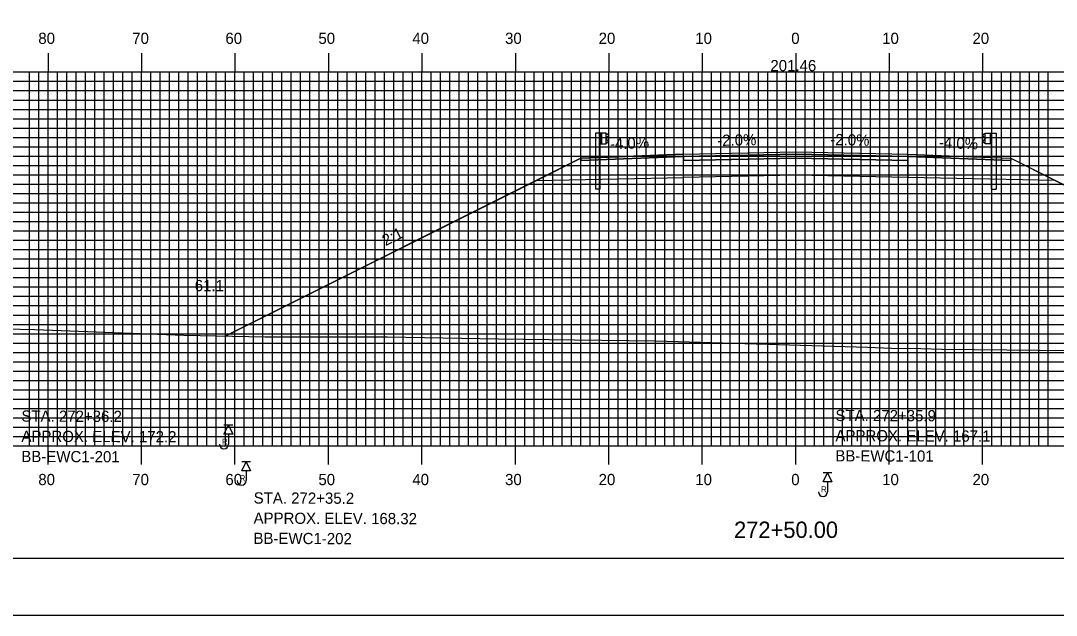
# Model space of a CAD drawing. Extents: x 1809013 to 1809356, y 442591 to 442811.
# Drawn here: x 1809095.4 to 1809206.2, y 442590.5 to 442654.2 of the extents above; entities that cross this region are included whole.
import ezdxf

# ---------------------------------------------------------------- set-up
doc = ezdxf.new("R2010")
doc.units = 0
for name, color, linetype in [('ANNOTATION', 7, 'Continuous'), ('BORDER', 7, 'Continuous'), ('BORING - REFUSAL', 7, 'Continuous'), ('D_Guardrail_Beam_Lt', 7, 'Continuous'), ('D_Guardrail_Beam_Rt', 7, 'Continuous'), ('D_Roadway_Centerline', 7, 'Continuous'), ('D_Roadway_Centerline_Text', 7, 'Continuous'), ('D_Roadway_Edge_Shoulder', 7, 'Continuous'), ('D_Roadway_Edge_TW', 7, 'Continuous'), ('D_Roadway_Pavement', 7, 'Continuous'), ('D_Roadway_SlopeLines', 7, 'Continuous'), ('D_Roadway_SubGrade', 7, 'Continuous'), ('D_Text_Standard', 7, 'Continuous'), ('H_V ANNOTATION', 7, 'Continuous'), ('MAJOR', 7, 'Continuous'), ('MINOR', 7, 'Continuous'), ('PLOT BOUNDARY', 7, 'Continuous'), ('S_Roadway_Centerline', 7, 'Continuous')]:
    doc.layers.add(name, color=color, linetype=linetype)

msp = doc.modelspace()

# ---------------------------------------------------------------- linework, layer by layer
at = {"layer": 'BORDER'}
msp.add_lwpolyline([(1809028.72, 442596.67), (1809348.72, 442596.67), (1809348.72, 442806.67), (1809028.72, 442806.67)], close=True, dxfattribs=at)
at = {"layer": 'BORING - REFUSAL'}
for p, q in [((1809118.1, 442610.87), (1809117.14, 442610.87)), ((1809117.62, 442609.91), (1809117.62, 442608.85)), ((1809120, 442606.97), (1809119.04, 442606.97)), ((1809119.52, 442606.01), (1809119.52, 442604.95)), ((1809182.2, 442605.77), (1809181.24, 442605.77)), ((1809181.72, 442604.81), (1809181.72, 442603.75))]:
    msp.add_line(p, q, dxfattribs=at)
for points in [[(1809117.62, 442610.87), (1809118.1, 442609.91), (1809117.14, 442609.91)], [(1809119.52, 442606.97), (1809120, 442606.01), (1809119.04, 442606.01)], [(1809181.72, 442605.77), (1809182.2, 442604.81), (1809181.24, 442604.81)]]:
    msp.add_lwpolyline(points, close=True, dxfattribs=at)
for centre in [(1809117.14, 442608.85), (1809119.04, 442604.95), (1809181.24, 442603.75)]:
    msp.add_arc(centre, 0.485, 180, 0, dxfattribs=at)
at = {"layer": 'D_Guardrail_Beam_Lt'}
for p, q in [((1809156.9, 442642.14), (1809156.9, 442636.14)), ((1809157.37, 442642.14), (1809156.9, 442642.14)), ((1809158.05, 442642.14), (1809157.37, 442642.14)), ((1809157.37, 442642.14), (1809157.37, 442640.98)), ((1809157.43, 442642.14), (1809157.43, 442640.98)), ((1809157.53, 442642.14), (1809157.53, 442640.98)), ((1809158.05, 442640.98), (1809158.05, 442642.14)), ((1809158.05, 442642.06), (1809158.13, 442642.05)), ((1809158.06, 442641.6), (1809158.06, 442641.53)), ((1809158.29, 442641.8), (1809158.09, 442641.66)), ((1809158.09, 442641.46), (1809158.29, 442641.32)), ((1809158.14, 442642.04), (1809158.29, 442641.94)), ((1809157.37, 442640.98), (1809158.05, 442640.98)), ((1809157.39, 442636.14), (1809157.39, 442640.98)), ((1809158.13, 442641.07), (1809158.05, 442641.06)), ((1809158.29, 442641.18), (1809158.14, 442641.08)), ((1809157.39, 442636.14), (1809156.9, 442636.14))]:
    msp.add_line(p, q, dxfattribs=at)
for centre, major_axis, start_param, end_param in [((1809158.14, 442641.6), (-0.0789, 0), 5.323254, 6.283185), ((1809158.14, 442641.53), (-0.0789, 0), 6.283185, 7.243116), ((1809158.12, 442642), (0.0417, 0), 0.959931, 1.376053), ((1809158.24, 442641.87), (0.0877, 0), 5.323254, 7.243116), ((1809158.24, 442641.25), (0.0877, 0), 5.323254, 7.243116), ((1809158.12, 442641.12), (0.0417, 0), 4.907132, 5.323254)]:
    msp.add_ellipse(centre, major_axis=major_axis, ratio=0.995501, start_param=start_param, end_param=end_param, dxfattribs=at)
at = {"layer": 'D_Guardrail_Beam_Rt'}
for p, q in [((1809198.51, 442642.04), (1809198.36, 442641.94)), ((1809198.36, 442641.8), (1809198.56, 442641.66)), ((1809198.56, 442641.46), (1809198.36, 442641.32)), ((1809198.6, 442642.06), (1809198.52, 442642.05)), ((1809198.59, 442641.6), (1809198.59, 442641.53)), ((1809198.6, 442642.14), (1809199.28, 442642.14)), ((1809198.6, 442640.98), (1809198.6, 442642.14)), ((1809199.12, 442642.14), (1809199.12, 442640.98)), ((1809199.22, 442642.14), (1809199.22, 442640.98)), ((1809199.28, 442642.14), (1809199.75, 442642.14)), ((1809199.28, 442642.14), (1809199.28, 442640.98)), ((1809199.75, 442642.14), (1809199.75, 442636.14)), ((1809198.36, 442641.18), (1809198.51, 442641.08)), ((1809198.52, 442641.07), (1809198.6, 442641.06)), ((1809199.28, 442640.98), (1809198.6, 442640.98)), ((1809199.26, 442636.14), (1809199.26, 442640.98)), ((1809199.26, 442636.14), (1809199.75, 442636.14))]:
    msp.add_line(p, q, dxfattribs=at)
for centre, major_axis, start_param, end_param in [((1809198.41, 442641.87), (-0.0877, 0), 5.323254, 7.243116), ((1809198.41, 442641.25), (-0.0877, 0), 5.323254, 7.243116), ((1809198.53, 442642), (-0.0417, 0), 4.907132, 5.323254), ((1809198.51, 442641.6), (0.0789, 0), 0, 0.959931), ((1809198.51, 442641.53), (0.0789, 0), 5.323254, 6.283185), ((1809198.53, 442641.12), (-0.0417, 0), 0.959931, 1.376053)]:
    msp.add_ellipse(centre, major_axis=major_axis, ratio=0.995501, start_param=start_param, end_param=end_param, dxfattribs=at)
at = {"layer": 'D_Roadway_Centerline'}
msp.add_lwpolyline([(1809117.27, 442620.41), (1809150.57, 442637.07), (1809155.32, 442639.44), (1809158.32, 442639.56), (1809166.32, 442639.88), (1809178.32, 442640.12), (1809190.32, 442639.88), (1809198.32, 442639.56), (1809201.32, 442639.44), (1809206.07, 442637.07), (1809243.63, 442618.29)], dxfattribs=at)
at = {"layer": 'D_Roadway_Edge_Shoulder'}
for points in [[(1809166.32, 442639.88), (1809158.32, 442639.56), (1809158.32, 442639.56), (1809155.32, 442639.44), (1809155.32, 442639.19), (1809166.32, 442639.63)], [(1809190.32, 442639.88), (1809198.32, 442639.56), (1809198.32, 442639.56), (1809201.32, 442639.44), (1809201.32, 442639.19), (1809190.32, 442639.63)]]:
    msp.add_lwpolyline(points, close=True, dxfattribs=at)
at = {"layer": 'D_Roadway_Edge_TW'}
msp.add_lwpolyline([(1809166.32, 442639.63), (1809166.32, 442639.88), (1809178.32, 442640.12), (1809190.32, 442639.88), (1809190.32, 442639.63), (1809178.32, 442639.87)], close=True, dxfattribs=at)
at = {"layer": 'D_Roadway_Pavement'}
msp.add_lwpolyline([(1809166.32, 442639.21), (1809166.32, 442639.63), (1809178.32, 442639.87), (1809190.32, 442639.63), (1809190.32, 442639.21), (1809178.32, 442639.45)], close=True, dxfattribs=at)
for points in [[(1809166.32, 442639.63), (1809166.32, 442639.21)], [(1809190.32, 442639.63), (1809190.32, 442639.21)]]:
    msp.add_lwpolyline(points, dxfattribs=at)
at = {"layer": 'D_Roadway_SlopeLines'}
for points in [[(1809155.32, 442639.44), (1809117.27, 442620.41)], [(1809201.32, 442639.44), (1809243.63, 442618.29)]]:
    msp.add_lwpolyline(points, dxfattribs=at)
at = {"layer": 'D_Roadway_SubGrade'}
for points in [[(1809166.32, 442639.21), (1809166.32, 442639.63), (1809155.32, 442639.19), (1809155.32, 442639.44), (1809150.57, 442637.07), (1809166.32, 442637.38)], [(1809166.32, 442637.38), (1809166.32, 442639.63), (1809166.32, 442639.21), (1809178.32, 442639.45), (1809190.32, 442639.21), (1809190.32, 442639.63), (1809190.32, 442637.38), (1809178.32, 442637.62)], [(1809190.32, 442639.21), (1809190.32, 442639.63), (1809201.32, 442639.19), (1809201.32, 442639.44), (1809206.07, 442637.07), (1809190.32, 442637.38)]]:
    msp.add_lwpolyline(points, close=True, dxfattribs=at)
at = {"layer": 'MAJOR'}
for p, q in [((1809098.32, 442650.67), (1809098.32, 442648.67)), ((1809108.32, 442650.67), (1809108.32, 442648.67)), ((1809118.32, 442650.67), (1809118.32, 442648.67)), ((1809128.32, 442650.67), (1809128.32, 442648.67)), ((1809138.32, 442650.67), (1809138.32, 442648.67)), ((1809148.32, 442650.67), (1809148.32, 442648.67)), ((1809158.32, 442650.67), (1809158.32, 442648.67)), ((1809168.32, 442650.67), (1809168.32, 442648.67)), ((1809178.32, 442650.67), (1809178.32, 442648.67)), ((1809188.32, 442650.67), (1809188.32, 442648.67)), ((1809198.32, 442650.67), (1809198.32, 442648.67)), ((1809038.32, 442648.67), (1809318.32, 442648.67)), ((1809038.32, 442648.67), (1809318.32, 442648.67)), ((1809098.32, 442608.67), (1809098.32, 442648.67)), ((1809108.32, 442608.67), (1809108.32, 442648.67)), ((1809118.32, 442608.67), (1809118.32, 442648.67)), ((1809128.32, 442608.67), (1809128.32, 442648.67)), ((1809138.32, 442608.67), (1809138.32, 442648.67)), ((1809148.32, 442608.67), (1809148.32, 442648.67)), ((1809158.32, 442608.67), (1809158.32, 442648.67)), ((1809168.32, 442608.67), (1809168.32, 442648.67)), ((1809178.32, 442608.67), (1809178.32, 442648.67)), ((1809188.32, 442608.67), (1809188.32, 442648.67)), ((1809198.32, 442608.67), (1809198.32, 442648.67)), ((1809038.32, 442643.67), (1809318.32, 442643.67)), ((1809038.32, 442638.67), (1809318.32, 442638.67)), ((1809038.32, 442633.67), (1809318.32, 442633.67)), ((1809038.32, 442628.67), (1809318.32, 442628.67)), ((1809038.32, 442623.67), (1809318.32, 442623.67)), ((1809038.32, 442618.67), (1809318.32, 442618.67)), ((1809038.32, 442613.67), (1809318.32, 442613.67)), ((1809038.32, 442608.67), (1809318.32, 442608.67)), ((1809038.32, 442608.67), (1809318.32, 442608.67)), ((1809098.32, 442606.66), (1809098.32, 442608.67)), ((1809108.32, 442606.66), (1809108.32, 442608.67)), ((1809118.32, 442606.66), (1809118.32, 442608.67)), ((1809128.32, 442606.66), (1809128.32, 442608.67)), ((1809138.32, 442606.66), (1809138.32, 442608.67)), ((1809148.32, 442606.66), (1809148.32, 442608.67)), ((1809158.32, 442606.66), (1809158.32, 442608.67)), ((1809168.32, 442606.66), (1809168.32, 442608.67)), ((1809178.32, 442606.66), (1809178.32, 442608.67)), ((1809188.32, 442606.66), (1809188.32, 442608.67)), ((1809198.32, 442606.66), (1809198.32, 442608.67))]:
    msp.add_line(p, q, dxfattribs=at)
at = {"layer": 'MINOR'}
for p, q in [((1809096.32, 442608.67), (1809096.32, 442648.67)), ((1809097.32, 442608.67), (1809097.32, 442648.67)), ((1809099.32, 442608.67), (1809099.32, 442648.67)), ((1809100.32, 442608.67), (1809100.32, 442648.67)), ((1809101.32, 442608.67), (1809101.32, 442648.67)), ((1809102.32, 442608.67), (1809102.32, 442648.67)), ((1809103.32, 442608.67), (1809103.32, 442648.67)), ((1809104.32, 442608.67), (1809104.32, 442648.67)), ((1809105.32, 442608.67), (1809105.32, 442648.67)), ((1809106.32, 442608.67), (1809106.32, 442648.67)), ((1809107.32, 442608.67), (1809107.32, 442648.67)), ((1809109.32, 442608.67), (1809109.32, 442648.67)), ((1809110.32, 442608.67), (1809110.32, 442648.67)), ((1809111.32, 442608.67), (1809111.32, 442648.67)), ((1809112.32, 442608.67), (1809112.32, 442648.67)), ((1809113.32, 442608.67), (1809113.32, 442648.67)), ((1809114.32, 442608.67), (1809114.32, 442648.67)), ((1809115.32, 442608.67), (1809115.32, 442648.67)), ((1809116.32, 442608.67), (1809116.32, 442648.67)), ((1809117.32, 442608.67), (1809117.32, 442648.67)), ((1809119.32, 442608.67), (1809119.32, 442648.67)), ((1809120.32, 442608.67), (1809120.32, 442648.67)), ((1809121.32, 442608.67), (1809121.32, 442648.67)), ((1809122.32, 442608.67), (1809122.32, 442648.67)), ((1809123.32, 442608.67), (1809123.32, 442648.67)), ((1809124.32, 442608.67), (1809124.32, 442648.67)), ((1809125.32, 442608.67), (1809125.32, 442648.67)), ((1809126.32, 442608.67), (1809126.32, 442648.67)), ((1809127.32, 442608.67), (1809127.32, 442648.67)), ((1809129.32, 442608.67), (1809129.32, 442648.67)), ((1809130.32, 442608.67), (1809130.32, 442648.67)), ((1809131.32, 442608.67), (1809131.32, 442648.67)), ((1809132.32, 442608.67), (1809132.32, 442648.67)), ((1809133.32, 442608.67), (1809133.32, 442648.67)), ((1809134.32, 442608.67), (1809134.32, 442648.67)), ((1809135.32, 442608.67), (1809135.32, 442648.67)), ((1809136.32, 442608.67), (1809136.32, 442648.67)), ((1809137.32, 442608.67), (1809137.32, 442648.67)), ((1809139.32, 442608.67), (1809139.32, 442648.67)), ((1809140.32, 442608.67), (1809140.32, 442648.67)), ((1809141.32, 442608.67), (1809141.32, 442648.67)), ((1809142.32, 442608.67), (1809142.32, 442648.67)), ((1809143.32, 442608.67), (1809143.32, 442648.67)), ((1809144.32, 442608.67), (1809144.32, 442648.67)), ((1809145.32, 442608.67), (1809145.32, 442648.67)), ((1809146.32, 442608.67), (1809146.32, 442648.67)), ((1809147.32, 442608.67), (1809147.32, 442648.67)), ((1809149.32, 442608.67), (1809149.32, 442648.67)), ((1809150.32, 442608.67), (1809150.32, 442648.67)), ((1809151.32, 442608.67), (1809151.32, 442648.67)), ((1809152.32, 442608.67), (1809152.32, 442648.67)), ((1809153.32, 442608.67), (1809153.32, 442648.67)), ((1809154.32, 442608.67), (1809154.32, 442648.67)), ((1809155.32, 442608.67), (1809155.32, 442648.67)), ((1809156.32, 442608.67), (1809156.32, 442648.67)), ((1809157.32, 442608.67), (1809157.32, 442648.67)), ((1809159.32, 442608.67), (1809159.32, 442648.67)), ((1809160.32, 442608.67), (1809160.32, 442648.67)), ((1809161.32, 442608.67), (1809161.32, 442648.67)), ((1809162.32, 442608.67), (1809162.32, 442648.67)), ((1809163.32, 442608.67), (1809163.32, 442648.67)), ((1809164.32, 442608.67), (1809164.32, 442648.67)), ((1809165.32, 442608.67), (1809165.32, 442648.67)), ((1809166.32, 442608.67), (1809166.32, 442648.67)), ((1809167.32, 442608.67), (1809167.32, 442648.67)), ((1809169.32, 442608.67), (1809169.32, 442648.67)), ((1809170.32, 442608.67), (1809170.32, 442648.67)), ((1809171.32, 442608.67), (1809171.32, 442648.67)), ((1809172.32, 442608.67), (1809172.32, 442648.67)), ((1809173.32, 442608.67), (1809173.32, 442648.67)), ((1809174.32, 442608.67), (1809174.32, 442648.67)), ((1809175.32, 442608.67), (1809175.32, 442648.67)), ((1809176.32, 442608.67), (1809176.32, 442648.67)), ((1809177.32, 442608.67), (1809177.32, 442648.67)), ((1809179.32, 442608.67), (1809179.32, 442648.67)), ((1809180.32, 442608.67), (1809180.32, 442648.67)), ((1809181.32, 442608.67), (1809181.32, 442648.67)), ((1809182.32, 442608.67), (1809182.32, 442648.67)), ((1809183.32, 442608.67), (1809183.32, 442648.67)), ((1809184.32, 442608.67), (1809184.32, 442648.67)), ((1809185.32, 442608.67), (1809185.32, 442648.67)), ((1809186.32, 442608.67), (1809186.32, 442648.67)), ((1809187.32, 442608.67), (1809187.32, 442648.67)), ((1809189.32, 442608.67), (1809189.32, 442648.67)), ((1809190.32, 442608.67), (1809190.32, 442648.67)), ((1809191.32, 442608.67), (1809191.32, 442648.67)), ((1809192.32, 442608.67), (1809192.32, 442648.67)), ((1809193.32, 442608.67), (1809193.32, 442648.67)), ((1809194.32, 442608.67), (1809194.32, 442648.67)), ((1809195.32, 442608.67), (1809195.32, 442648.67)), ((1809196.32, 442608.67), (1809196.32, 442648.67)), ((1809197.32, 442608.67), (1809197.32, 442648.67)), ((1809199.32, 442608.67), (1809199.32, 442648.67)), ((1809200.32, 442608.67), (1809200.32, 442648.67)), ((1809201.32, 442608.67), (1809201.32, 442648.67)), ((1809202.32, 442608.67), (1809202.32, 442648.67)), ((1809203.32, 442608.67), (1809203.32, 442648.67)), ((1809204.32, 442608.67), (1809204.32, 442648.67)), ((1809205.32, 442608.67), (1809205.32, 442648.67)), ((1809038.32, 442647.67), (1809318.32, 442647.67)), ((1809038.32, 442646.67), (1809318.32, 442646.67)), ((1809038.32, 442645.67), (1809318.32, 442645.67)), ((1809038.32, 442644.67), (1809318.32, 442644.67)), ((1809038.32, 442642.67), (1809318.32, 442642.67)), ((1809038.32, 442641.67), (1809318.32, 442641.67)), ((1809038.32, 442640.67), (1809318.32, 442640.67)), ((1809038.32, 442639.67), (1809318.32, 442639.67)), ((1809038.32, 442637.67), (1809318.32, 442637.67)), ((1809038.32, 442636.67), (1809318.32, 442636.67)), ((1809038.32, 442635.67), (1809318.32, 442635.67)), ((1809038.32, 442634.67), (1809318.32, 442634.67)), ((1809038.32, 442632.67), (1809318.32, 442632.67)), ((1809038.32, 442631.67), (1809318.32, 442631.67)), ((1809038.32, 442630.67), (1809318.32, 442630.67)), ((1809038.32, 442629.67), (1809318.32, 442629.67)), ((1809038.32, 442627.67), (1809318.32, 442627.67)), ((1809038.32, 442626.67), (1809318.32, 442626.67)), ((1809038.32, 442625.67), (1809318.32, 442625.67)), ((1809038.32, 442624.67), (1809318.32, 442624.67)), ((1809038.32, 442622.67), (1809318.32, 442622.67)), ((1809038.32, 442621.67), (1809318.32, 442621.67)), ((1809038.32, 442620.67), (1809318.32, 442620.67)), ((1809038.32, 442619.67), (1809318.32, 442619.67)), ((1809038.32, 442617.67), (1809318.32, 442617.67)), ((1809038.32, 442616.67), (1809318.32, 442616.67)), ((1809038.32, 442615.67), (1809318.32, 442615.67)), ((1809038.32, 442614.67), (1809318.32, 442614.67)), ((1809038.32, 442612.67), (1809318.32, 442612.67)), ((1809038.32, 442611.67), (1809318.32, 442611.67)), ((1809038.32, 442610.67), (1809318.32, 442610.67)), ((1809038.32, 442609.67), (1809318.32, 442609.67))]:
    msp.add_line(p, q, dxfattribs=at)
at = {"layer": 'PLOT BOUNDARY'}
msp.add_lwpolyline([(1809012.54, 442590.55), (1809352.54, 442590.55), (1809352.54, 442810.55), (1809012.54, 442810.55)], close=True, dxfattribs=at)
at = {"layer": 'S_Roadway_Centerline'}
msp.add_lwpolyline([(1809038.32, 442622.97), (1809043.49, 442622.48), (1809049.88, 442622.16), (1809058.12, 442622.14), (1809070.64, 442621.8), (1809078.23, 442621.76), (1809091.25, 442621.32), (1809093.8, 442621.19), (1809096.91, 442621.11), (1809112.84, 442620.5), (1809121.56, 442620.32), (1809134.65, 442620.35), (1809146.51, 442620.13), (1809154.66, 442620.03), (1809163.34, 442619.91), (1809185.99, 442619.22), (1809188.55, 442619.14), (1809191.72, 442619.08), (1809193.97, 442619.02), (1809218.3, 442618.76)], dxfattribs=at)

# ---------------------------------------------------------------- texts
at = {"layer": 'ANNOTATION'}
for s, rotation, p in [('-4.0%', 2.2906, (1809158.46, 442640.37)), ('-2.0%', 1.1458, (1809169.93, 442640.75)), ('-2.0%', 358.8542, (1809182.01, 442640.85)), ('-4.0%', 357.7094, (1809193.62, 442640.55)), ('2:1', 26.5651, (1809134.44, 442630.03))]:
    msp.add_text(s, height=1.2, rotation=rotation, dxfattribs=at).set_placement(p)
at = {"layer": 'BORING - REFUSAL'}
for s, p in [('STA. 272+36.2', (1809095.47, 442611.26)), ('STA. 272+35.9', (1809182.57, 442611.33)), ('APPROX. ELEV. 172.2', (1809095.47, 442609.1)), ('APPROX. ELEV. 167.1', (1809182.57, 442609.17)), ('BB-EWC1-201', (1809095.46, 442606.94)), ('BB-EWC1-101', (1809182.56, 442607.01)), ('STA. 272+35.2', (1809120.32, 442602.5)), ('APPROX. ELEV. 168.32', (1809120.31, 442600.34)), ('BB-EWC1-202', (1809120.3, 442598.18))]:
    msp.add_text(s, height=1.2, rotation=359.8142, dxfattribs=at).set_placement(p)
for p in [(1809116.92, 442608.79), (1809118.82, 442604.89), (1809181.02, 442603.69)]:
    msp.add_text('R', height=0.64, dxfattribs=at).set_placement(p)
at = {"layer": 'D_Roadway_Centerline'}
for s, p in [('C', (1809178.32, 442640.12)), ('L', (1809178.32, 442640.11))]:
    msp.add_text(s, height=0.0146, dxfattribs=at).set_placement(p)
at = {"layer": 'D_Roadway_Centerline_Text'}
msp.add_text('201.46', height=1.2, dxfattribs=at).set_placement((1809175.61, 442648.75))
at = {"layer": 'D_Text_Standard'}
msp.add_text("61.1'", height=1.2, dxfattribs=at).set_placement((1809114.02, 442625.22))
at = {"layer": 'H_V ANNOTATION'}
for s, height, p in [('80', 1.2, (1809097.28, 442651.67)), ('70', 1.2, (1809107.33, 442651.67)), ('60', 1.2, (1809117.3, 442651.67)), ('50', 1.2, (1809127.25, 442651.67)), ('40', 1.2, (1809137.3, 442651.67)), ('30', 1.2, (1809147.22, 442651.67)), ('20', 1.2, (1809157.23, 442651.67)), ('10', 1.2, (1809167.57, 442651.67)), ('0', 1.2, (1809177.84, 442651.67)), ('10', 1.2, (1809187.57, 442651.67)), ('20', 1.2, (1809197.23, 442651.67)), ('80', 1.2, (1809097.28, 442604.47)), ('70', 1.2, (1809107.33, 442604.47)), ('60', 1.2, (1809117.3, 442604.47)), ('50', 1.2, (1809127.25, 442604.47)), ('40', 1.2, (1809137.3, 442604.47)), ('30', 1.2, (1809147.22, 442604.47)), ('20', 1.2, (1809157.23, 442604.47)), ('10', 1.2, (1809167.57, 442604.47)), ('0', 1.2, (1809177.84, 442604.47)), ('10', 1.2, (1809187.57, 442604.47)), ('20', 1.2, (1809197.23, 442604.47)), ('272+50.00', 1.75, (1809171.72, 442598.82))]:
    msp.add_text(s, height=height, dxfattribs=at).set_placement(p)

doc.saveas('drawing.dxf')
